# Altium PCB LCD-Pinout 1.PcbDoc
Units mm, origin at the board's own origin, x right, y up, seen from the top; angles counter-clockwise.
Board outline 42 x 31 mm, 2 copper layers (Top Layer, Bottom Layer); 4 components, 14 nets, 50 pads, 0 vias.
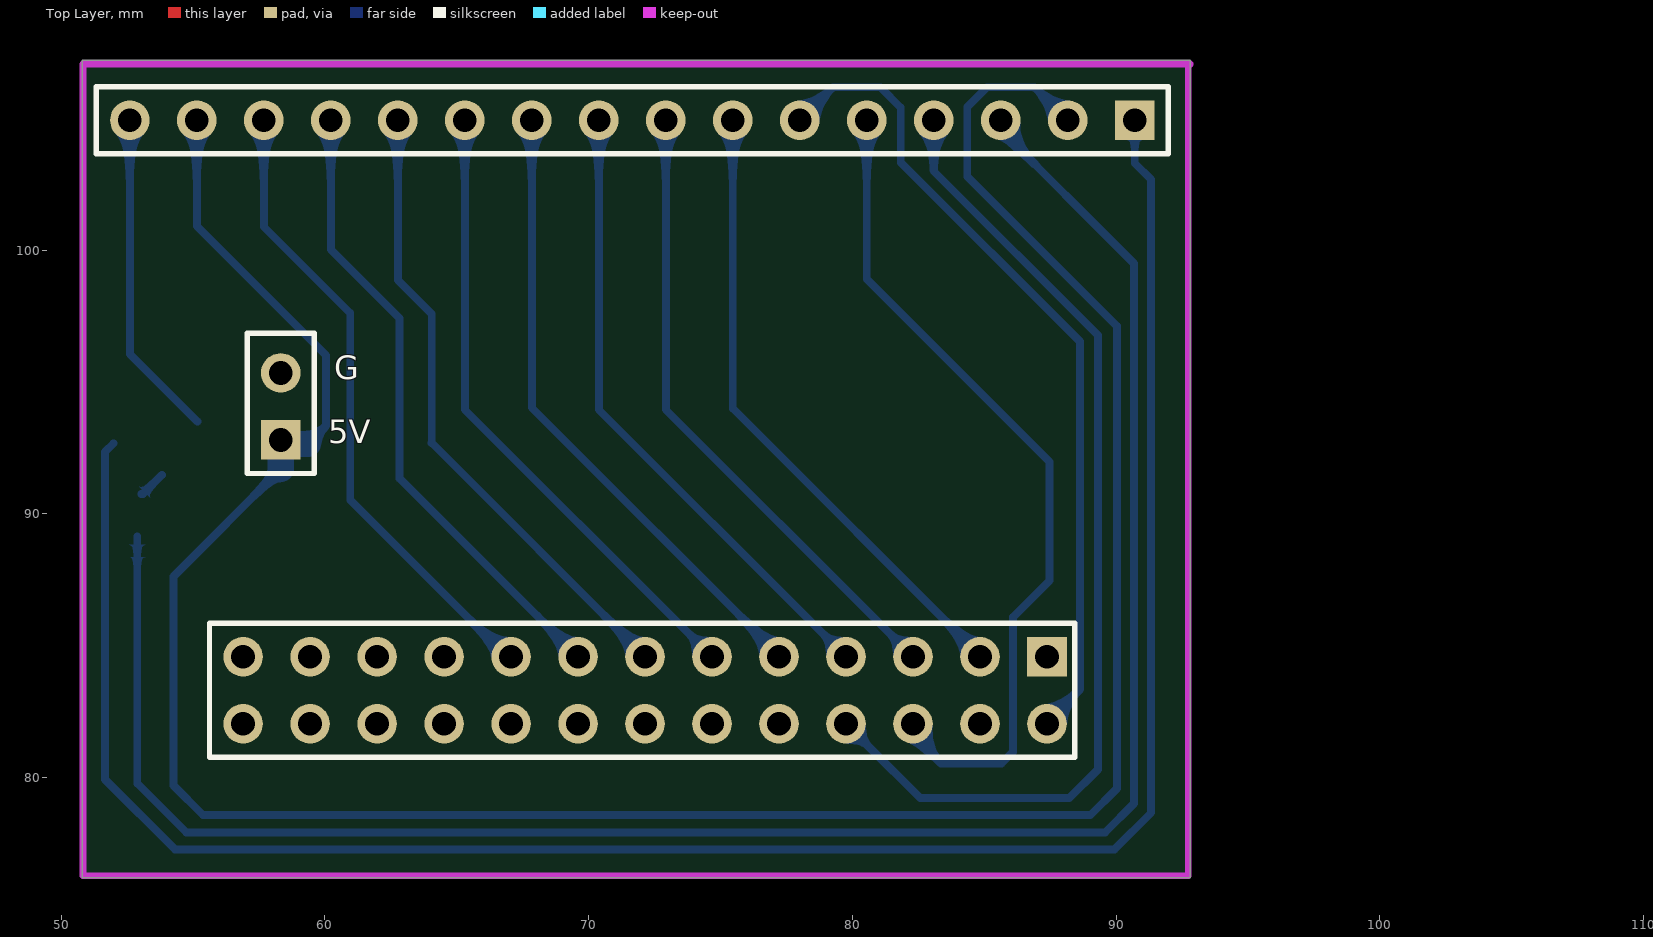
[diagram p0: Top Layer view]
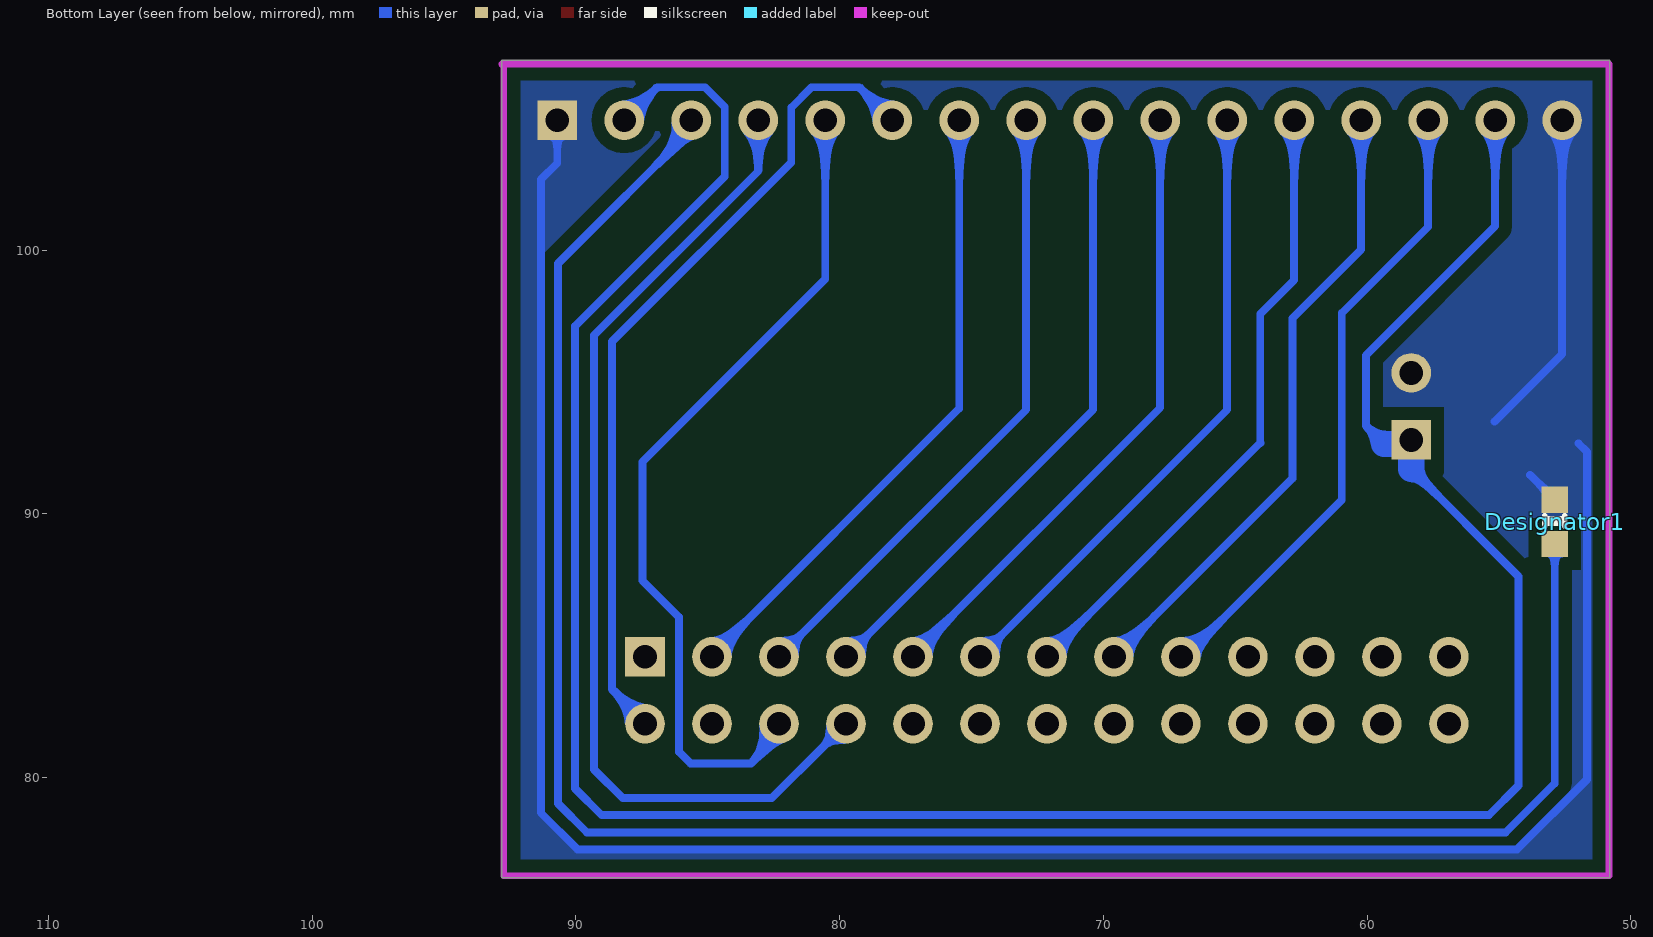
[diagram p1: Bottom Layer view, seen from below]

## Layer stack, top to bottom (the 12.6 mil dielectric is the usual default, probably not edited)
Top Solder: solder mask 0.0102, Solder Resist, Dk 3.5
Top Layer: signal copper 0.0356
Dielectric 1: dielectric 0.32, FR-4, Dk 4.8
Bottom Layer: signal copper 0.0356
Bottom Solder: solder mask 0.0102, Solder Resist, Dk 3.5

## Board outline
50.8,76.2 92.8,76.2 92.8,107.2 50.8,107.2

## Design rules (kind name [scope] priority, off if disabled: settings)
Clearance [All] p1: gap=0.35 ignorepadtopadclearanceinfootprint=FALSE except(0: Arc-Hole Track-Hole SMDPad-Hole THPad-Hole Via-Hole Fill-Hole Poly-Hole Region-Hole Text-Hole; 0.5: Arc-Poly Track-Poly SMDPad-Poly THPad-Poly Via-Poly Fill-Poly Poly-Poly)
PolygonConnect PolygonConnect_1 [All vs IsNamedPolygon('Top Layer-No Net')] p1: connectstyle=Direct reliefconductorwidth=0.254 reliefentries=4 polygonreliefangle="90 Angle" airgapwidth=0.254
PolygonConnect [All] p2: connectstyle=Relief reliefconductorwidth=0.254 reliefentries=4 polygonreliefangle="90 Angle" airgapwidth=0.254
RoutingVias [All] p1: holewidth=0.8 width=1.6 viastyle="Through Hole" minholewidth=0.711 minwidth=1.27 maxholewidth=0.711 maxwidth=1.27
SilkToSilkClearance [All] p1: silktosilkclearance=0.1
SilkToSolderMaskClearance [IsPad] p1: minsilkscreentomaskgap=0.1 clearancetoexposedcopper=TRUE
SolderMaskExpansion [All] p1: expansion=0.102 istentingtop=FALSE
Width [All] p1: maxlimit=0.3 minlimit=0.3 preferedwidth=0.3
28 further rules are at their usual default settings.

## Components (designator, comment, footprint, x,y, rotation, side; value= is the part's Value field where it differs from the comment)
Designator1 "Comment" J1-0603 52.883,89.611 r270 bottom (schematic designator R1)
P1 "Header 16" HDR1X16 90.703,104.927 r180 top
P2 "Header 13X2A" HDR2X13_CEN 87.376,84.582 r180 top
P3 "Header 4" HDR1X4 58.326,92.807 r90 top

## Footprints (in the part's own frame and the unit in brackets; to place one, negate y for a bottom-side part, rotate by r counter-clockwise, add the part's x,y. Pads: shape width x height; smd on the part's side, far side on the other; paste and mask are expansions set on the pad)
HDR1X4 [mm] "Connector; Header; 4 Position"
  rect 1.5x1.5 hole 0.9: 1(0,0)
  round 1.5 hole 0.9: 2(2.54,0)
  silkscreen extent -1.27,-1.27 4.04,1.27
HDR1X16 [mm] "Connector; Header; 16 Position"
  rect 1.5x1.5 hole 0.9: 1(0,0)
  round 1.5 hole 0.9: 2(2.54,0) 3(5.08,0) 4(7.62,0) 5(10.16,0) 6(12.7,0) 7(15.24,0) 8(17.78,0) 9(20.32,0) 10(22.86,0) 11(25.4,0) 12(27.94,0) 13(30.48,0) 14(33.02,0) 15(35.56,0) 16(38.1,0)
  silkscreen extent -1.27,-1.27 39.37,1.27
HDR2X13_CEN [mm] "Connector; Header; 13x2 Position"
  rect 1.5x1.5 hole 0.9: 1(0,0)
  round 1.5 hole 0.9: 2(2.54,0) 3(5.08,0) 4(7.62,0) 5(10.16,0) 6(12.7,0) 7(15.24,0) 8(17.78,0) 9(20.32,0) 10(22.86,0) 11(25.4,0) 12(27.94,0) 13(30.48,0) 14(0,2.54) 15(2.54,2.54) 16(5.08,2.54) 17(7.62,2.54) 18(10.16,2.54) 19(12.7,2.54) 20(15.24,2.54) 21(17.78,2.54) 22(20.32,2.54) 23(22.86,2.54) 24(25.4,2.54) 25(27.94,2.54) 26(30.48,2.54)
  silkscreen extent -1.06,-1.27 31.75,3.81
J1-0603 [mm] "Chip Resistor, Body 1.6x0.8mm, IPC High Density"
  rect 1x1 smd: 1(-0.932,0) 2(0.75,0)
  silkscreen extent -0.32,-0.38 0.08,0.38, body extent -0.85,-0.48 0.85,0.48, height 0.9

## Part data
Designator1: library part Res3, "Resistor"
P1: "Header, 16-Pin"
P2: "Header, 13-Pin, Dual row"
P3: "Header, 4-Pin"

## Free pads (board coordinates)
  round 0 on Mech16 paste+0 mask+0: 1(51.851,106.5) 1(81.153,98.806) 1(100.33,97.536) 1(108.712,103.378)

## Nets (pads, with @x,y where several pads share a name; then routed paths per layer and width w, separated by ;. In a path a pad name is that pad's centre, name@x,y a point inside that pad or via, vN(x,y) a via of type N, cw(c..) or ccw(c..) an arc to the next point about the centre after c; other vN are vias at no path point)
GND: Designator1.1 P1.1 P1.16 P3.2 | length 93.9
  Bottom Layer w0.3: 51.989,92.68 51.664,92.354 51.664,79.934 54.32,77.278 89.932,77.278 91.328,78.674 91.328,102.677 90.703,103.302 P1.1 ; P1.16@52.603,104.546 52.603,96.063 55.169,93.497 ; Designator1.1@53.035,90.754 53.094,90.754 53.824,91.484
NetP1_3: Designator1.2 P1.3 | length 76.3
  Bottom Layer w0.3: Designator1.2@52.883,89.154 52.883,79.786 54.741,77.928 89.586,77.928 90.678,79.019 90.678,99.492 P1.3@85.433,104.737
NetP1_4: P1.4 P2.17 | length 37.2
  Bottom Layer w0.3: 80.594,81.204 82.57,79.228 88.219,79.228 89.306,80.315 89.306,96.774 83.083,102.997 P1.4
NetP1_5: P1.5 P2.16 | length 32
  Bottom Layer w0.3: P1.5 80.543,98.908 87.478,91.973 87.478,87.478 86.086,86.086 86.086,80.981 85.649,80.543 83.363,80.543 P2.16@82.372,81.534 ; P2.16@82.296,81.717 P2.16
NetP1_6: P1.6 P2.14 | length 31.3
  Bottom Layer w0.3: P1.6 79.253,106.177 81.061,106.177 81.833,105.405 81.833,103.328 88.626,96.535 88.626,83.353 P2.14@87.376,82.103
NetP1_7: P1.7 P2.2 | length 23.8
  Bottom Layer w0.3: P1.7@75.463,104.546 75.463,94.005 P2.2@84.836,84.633
NetP1_8: P1.8 P2.3 | length 22.7
  Bottom Layer w0.3: P1.8@72.923,104.546 72.923,93.955 81.458,85.42
NetP1_9: P1.9 P2.4 | length 22.7
  Bottom Layer w0.3: P1.9@70.383,104.546 70.383,93.955 78.918,85.42
NetP1_10: P1.10 P2.5 | length 23.8
  Bottom Layer w0.3: P1.10@67.843,104.546 67.843,94.031 P2.5@77.254,84.62
NetP1_11: P1.11 P2.6 | length 22.7
  Bottom Layer w0.3: P1.11@65.303,104.546 65.303,93.955 73.838,85.42
NetP1_12: P1.12 P2.7 | length 23.8
  Bottom Layer w0.3: P1.12@62.763,104.546 62.763,98.866 64.051,97.579 64.051,92.702 ; 64.046,92.697 P2.7@72.136,84.607
NetP1_13: P1.13 P2.8 | length 23.8
  Bottom Layer w0.3: P1.13@60.223,104.546 60.223,100.025 62.829,97.419 62.829,91.349 P2.8
NetP1_14: P1.14 P2.9 | length 24.2
  Bottom Layer w0.3: P1.14 57.683,100.889 60.96,97.612 60.96,90.526 P2.9@66.904,84.582
VCC: P1.2 P1.15 P3.1 | length 99.3
  Bottom Layer w0.3: P1.15@55.143,104.546 55.143,100.914 60.046,96.012 60.046,93.345 59.351,92.65 ; 58.326,91.702 54.254,87.63 54.254,79.705 55.382,78.578 89.017,78.578 90.028,79.589 90.028,97.119 84.353,102.794 84.353,105.425 85.106,106.177 86.913,106.177 P1.2 ; P3.1@58.926,92.225 P3.1@58.926,92.65
  Bottom Layer w1: 58.326,91.702 P3.1 ; P3.1@58.926,92.65 59.351,92.65
pads on no net: P2.1 P2.10 P2.11 P2.12 P2.13 P2.15 P2.18 P2.19 P2.20 P2.21 P2.22 P2.23 P2.24 P2.25 P2.26

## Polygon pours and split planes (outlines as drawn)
GND on Bottom Layer "Top Layer-No Net" (solid, remove dead copper, pour order 18): 92.735,106.985 92.735,76.505 50.825,76.505 50.825,107.061

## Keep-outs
Keep-Out Layer:
  lines w0.254: 50.825,107.061 50.825,76.276 92.735,76.276 92.735,106.985 92.812,107.061 50.927,107.061

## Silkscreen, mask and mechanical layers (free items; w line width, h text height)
Top Overlay:
  text "G" at 60.35,94.811 h1.52
  text "5V" at 60.122,92.372 h1.52
Bottom Overlay:
  rectangle: 52.502,89.535 53.264,89.916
